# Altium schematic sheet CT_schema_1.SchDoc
size 456 x 431 mm
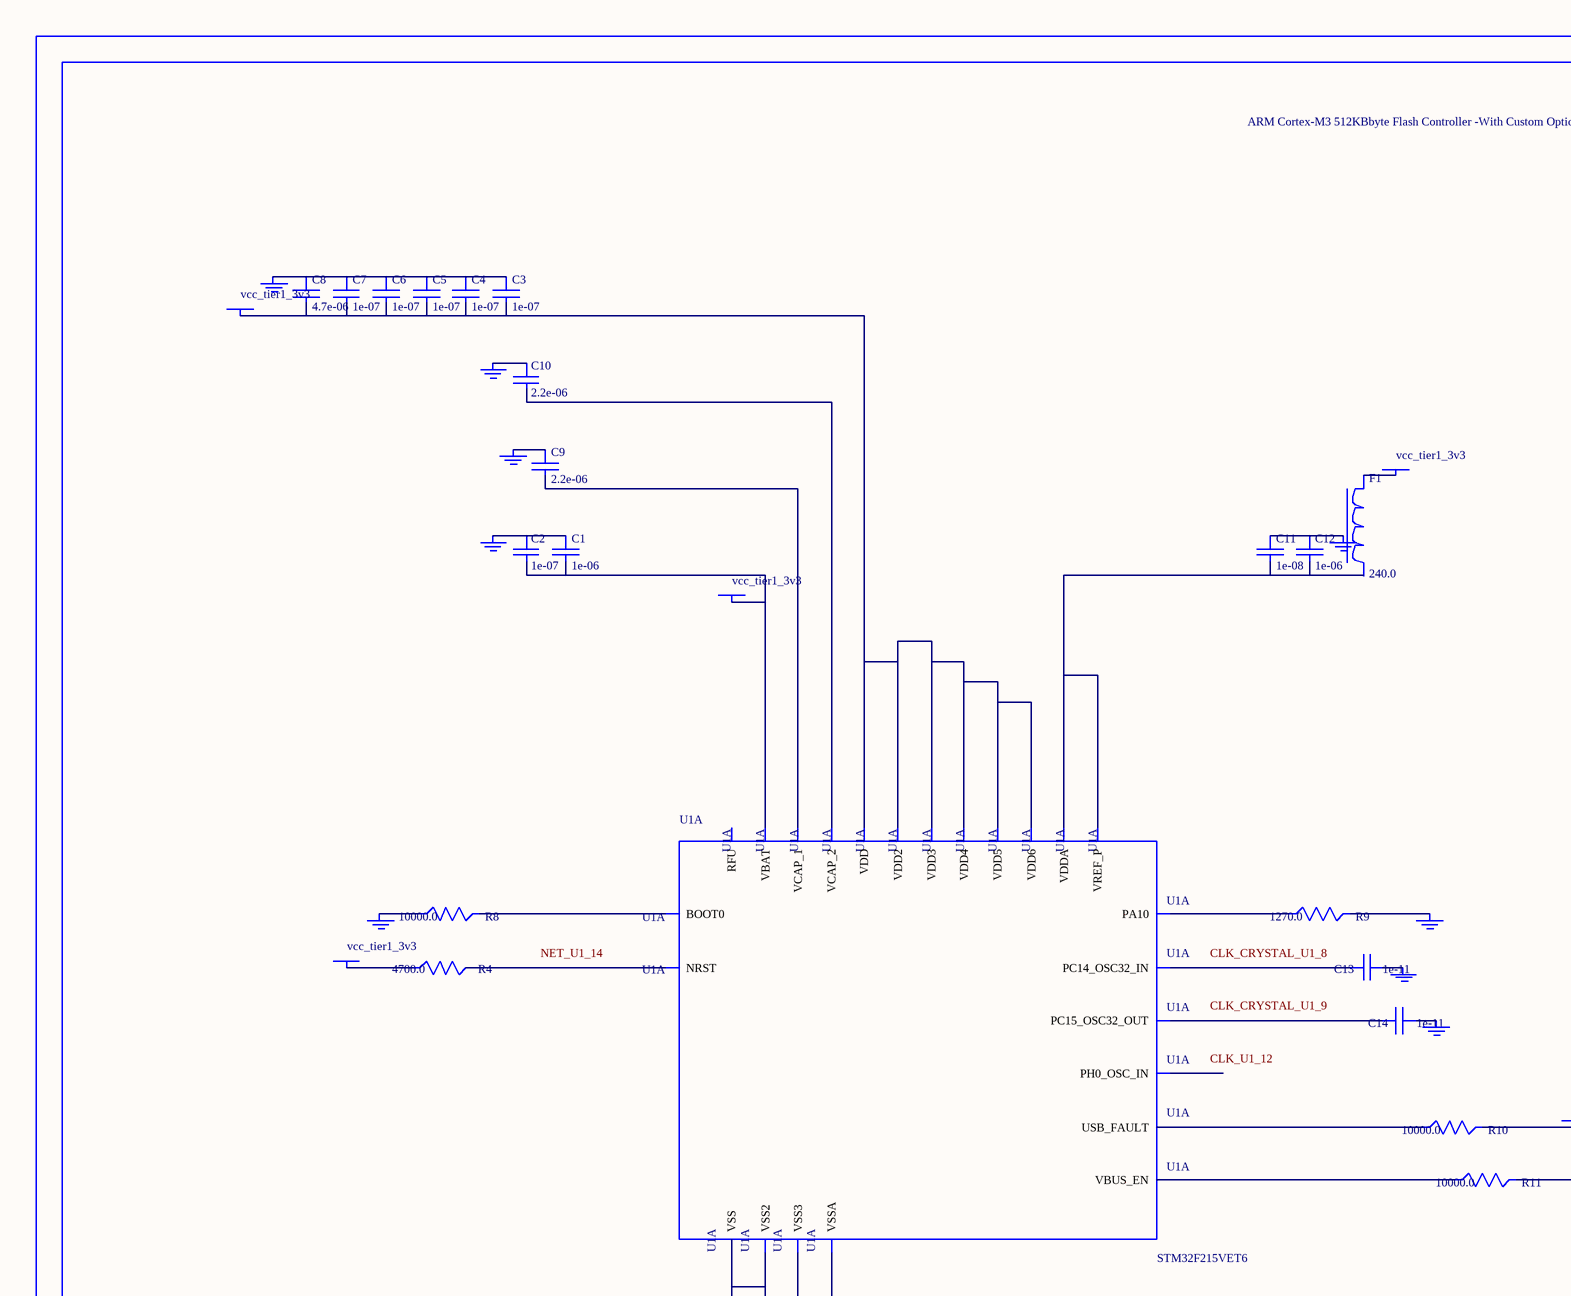
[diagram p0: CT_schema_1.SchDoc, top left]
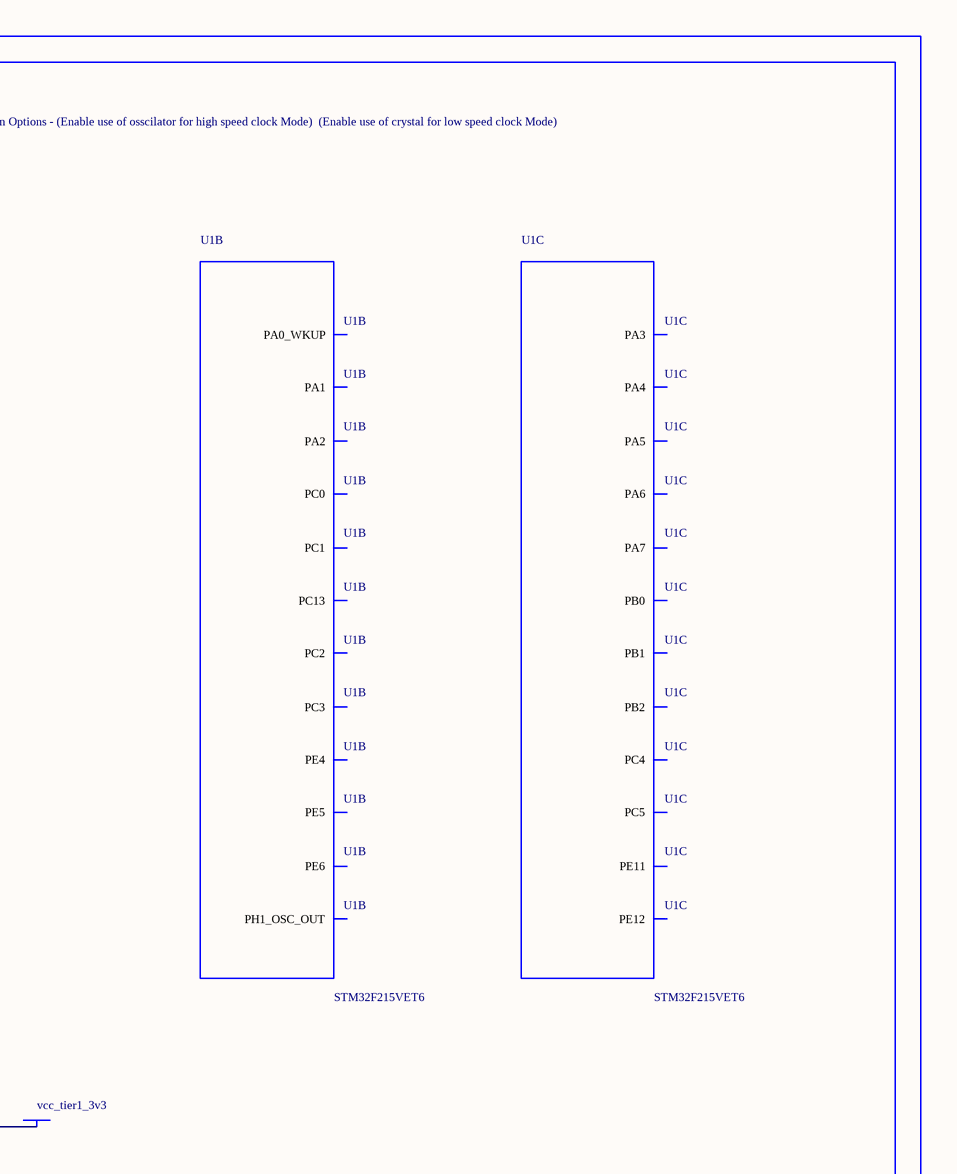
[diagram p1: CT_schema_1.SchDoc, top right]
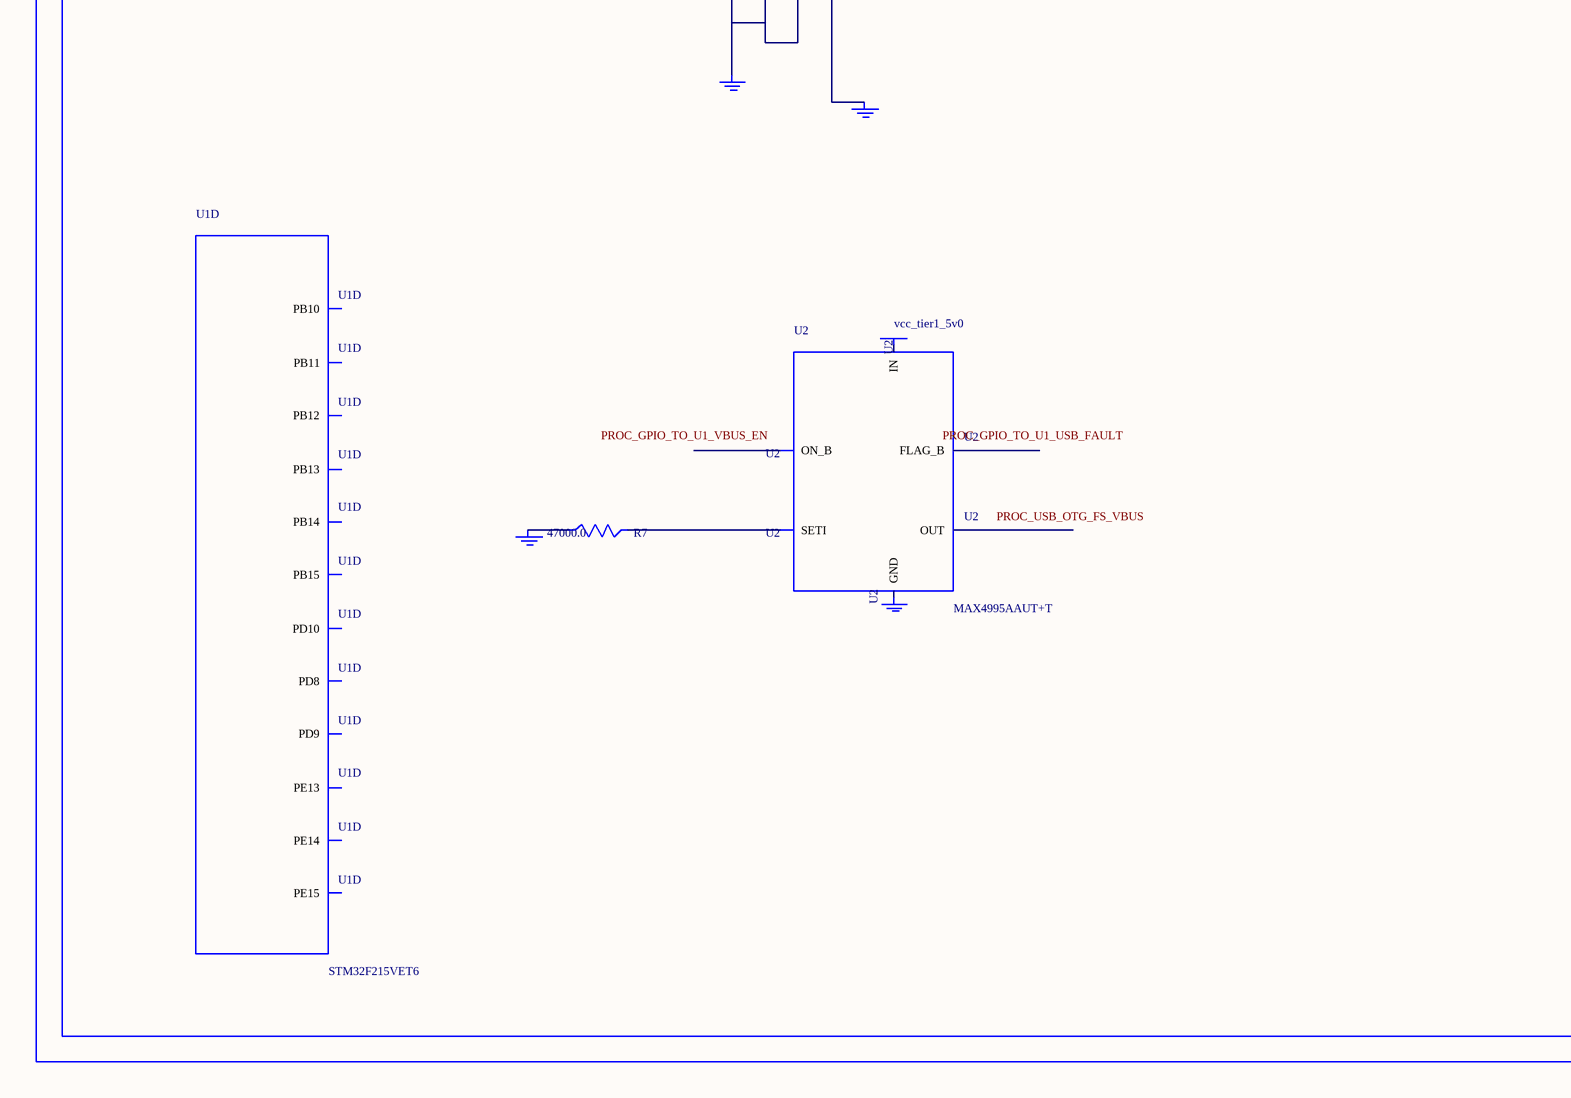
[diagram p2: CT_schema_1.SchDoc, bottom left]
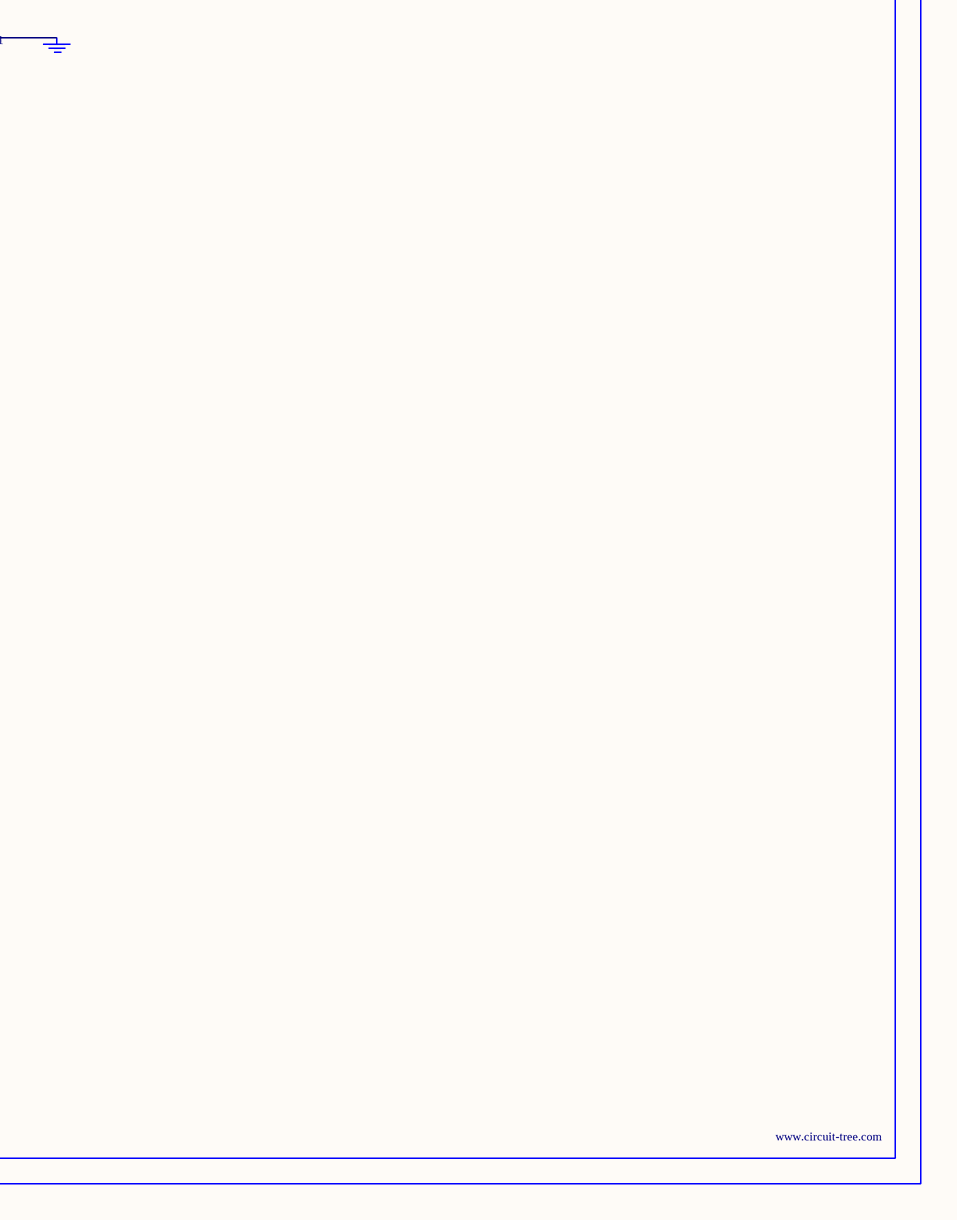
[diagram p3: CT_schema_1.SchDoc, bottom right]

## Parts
BORDER0  (no value)
C1  1e-06  [C0603]
C2  1e-07  [C0603]
C3  1e-07  [C0603]
C4  1e-07  [C0603]
C5  1e-07  [C0603]
C6  1e-07  [C0603]
C7  1e-07  [C0603]
C8  4.7e-06  [C0603]
C9  2.2e-06  [C0603]
C10  2.2e-06  [C0603]
C11  1e-08  [C0603]
C12  1e-06  [C0603]
C13  1e-11  [C0402]
C14  1e-11  [C0402]
F1  240.0  [L0603]
GND_INSTANCE_0_0  (no value)
GND_INSTANCE_0_1  (no value)
GND_INSTANCE_0_2  (no value)
GND_INSTANCE_0_3  (no value)
GND_INSTANCE_0_4  (no value)
GND_INSTANCE_0_5  (no value)
GND_INSTANCE_0_6  (no value)
GND_INSTANCE_0_7  (no value)
GND_INSTANCE_0_8  (no value)
GND_INSTANCE_0_9  (no value)
GND_INSTANCE_0_10  (no value)
GND_INSTANCE_0_11  (no value)
GND_INSTANCE_0_12  (no value)
GND_INSTANCE_0_13  (no value)
POWER_INSTANCE_0_0  vcc_tier1_3v3
POWER_INSTANCE_0_1  vcc_tier1_3v3
POWER_INSTANCE_0_2  vcc_tier1_3v3
POWER_INSTANCE_0_3  vcc_tier1_3v3
POWER_INSTANCE_0_4  vcc_tier1_3v3
POWER_INSTANCE_0_5  vcc_tier1_5v0
R4  4700.0  [R0603]
R7  47000.0  [R0603]
R8  10000.0  [R0603]
R9  1270.0  [R0603]
R10  10000.0  [R0603]
R11  10000.0  [R0603]
U1  STM32F215VET6  [LQFP100]  (parts A,B,C,D of 9)
U2  MAX4995AAUT+T  [SOT-23-6]

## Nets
NetC1_1: C1.1 C2.1 GND_INSTANCE_0_1.0(GND)
NetC1_2: C1.2 C2.2 POWER_INSTANCE_0_1.0(PWR) U1.6(VBAT)
NetC3_1: C3.1 C4.1 C5.1 C6.1 C7.1 C8.1 GND_INSTANCE_0_4.0(GND)
NetC3_2: C3.2 C4.2 C5.2 C6.2 C7.2 C8.2 POWER_INSTANCE_0_2.0(PWR) U1.11(VDD) U1.19(VDD2) U1.28(VDD3) U1.50(VDD4) U1.75(VDD5) U1.100(VDD6)
NetC9_1: C9.1 GND_INSTANCE_0_7.0(GND)
NetC9_2: C9.2 U1.49(VCAP_1)
NetC10_1: C10.1 GND_INSTANCE_0_9.0(GND)
NetC10_2: C10.2 U1.73(VCAP_2)
NetC11_1: C11.1 C12.1 GND_INSTANCE_0_6.0(GND)
NetC11_2: C11.2 C12.2 U1.21(VREF_P) U1.22(VDDA)
NetC13_1: C13.1 GND_INSTANCE_0_2.0(GND)
NetC13_2: C13.2 U1.8(PC14_OSC32_IN)
NetC14_1: C14.1 GND_INSTANCE_0_3.0(GND)
NetC14_2: C14.2 U1.9(PC15_OSC32_OUT)
NetF1_1: F1.1 POWER_INSTANCE_0_3.0(PWR)
NetGND_INSTANCE_0_0_0: GND_INSTANCE_0_0.0(GND) R11.2
NetGND_INSTANCE_0_5_0: GND_INSTANCE_0_5.0(GND) U1.20(VSSA)
NetGND_INSTANCE_0_8_0: GND_INSTANCE_0_8.0(GND) R9.2
NetGND_INSTANCE_0_10_0: GND_INSTANCE_0_10.0(GND) R8.1
NetGND_INSTANCE_0_11_0: GND_INSTANCE_0_11.0(GND) U1.10(VSS) U1.27(VSS2) U1.74(VSS3)
NetGND_INSTANCE_0_12_0: GND_INSTANCE_0_12.0(GND) R7.1
NetPOWER_INSTANCE_0_0_0: POWER_INSTANCE_0_0.0(PWR) R10.2
NetPOWER_INSTANCE_0_4_0: POWER_INSTANCE_0_4.0(PWR) R4.1
NetR4_2: R4.2 U1.14(NRST)
NetR7_2: R7.2 U2.3(SETI)
NetR8_2: R8.2 U1.94(BOOT0)
NetR9_1: R9.1 U1.69(PA10)
NetR10_1: R10.1 U1.2(USB_FAULT)
NetR11_1: R11.1 U1.1(VBUS_EN)

Not connected (* = marked no-connect by the designer): F1 2; GND_INSTANCE_0_13 0(GND); POWER_INSTANCE_0_5 0(PWR); U1 3(PE4) 4(PE5) 5(PE6) 7(PC13) 12(PH0_OSC_IN) 13(PH1_OSC_OUT) 15(PC0) 16(PC1) 17(PC2) 18(PC3) 23(PA0_WKUP) 24(PA1) 25(PA2) 26(PA3) 29(PA4) 30(PA5) 31(PA6) 32(PA7) 33(PC4) 34(PC5) 35(PB0) 36(PB1) 37(PB2) 42(PE11) 43(PE12) 44(PE13) 45(PE14) 46(PE15) 47(PB10) 48(PB11) 51(PB12) 52(PB13) 53(PB14) 54(PB15) 55(PD8) 56(PD9) 57(PD10) 99(RFU); U2 1(OUT) 2(GND) 4(ON_B) 5(IN) 6(FLAG_B)

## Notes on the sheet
- Labels drawn without touching a wire or pin: CLK_CRYSTAL_U1_8, CLK_CRYSTAL_U1_9, CLK_U1_12, NET_U1_14, PROC_GPIO_TO_U1_USB_FAULT, PROC_GPIO_TO_U1_VBUS_EN, PROC_USB_OTG_FS_VBUS

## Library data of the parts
BORDER0 = BORDER_PAGE0
C1 C12 = C0603C105K3RACTU
C2-C7 = 06035C104K4Z2A
C8 = GRM188R6YA475KE15D
C9 C10 = C0603C225K8RACTU
C11 = 06035C103K4Z2A
C13 C14 = C0402C100K3GACTU
F1 = Z0603C241ASMST
GND_INSTANCE_0_0-GND_INSTANCE_0_13 = GND
POWER_INSTANCE_0_0-POWER_INSTANCE_0_5 = PWR
R4 = RC0603JR-074K7L
R7 = RC0603JR-0747KL
R8 R10 R11 = RC0603JR-0710KL
R9 = RC0603FR-071K27L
